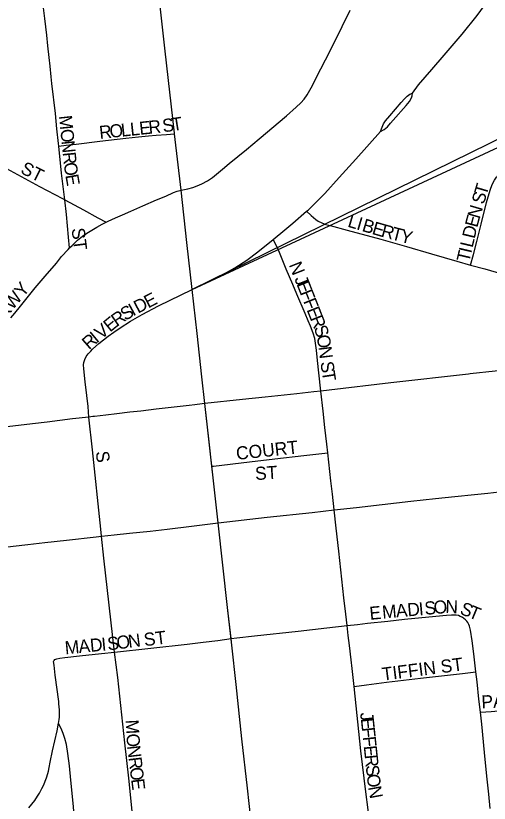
# Model space of a CAD drawing. Extents: x 1772825 to 1773716, y 1138558 to 1139032.
# Drawn here: x 1773349.44 to 1773356.3, y 1138869.86 to 1138881.27 of the extents above; entities that cross this region are included whole.
import ezdxf

# ---------------------------------------------------------------- set-up
doc = ezdxf.new("R2010")
doc.units = 0
for name, color, linetype in [('Default', 7, 'Continuous'), ('GM_X_City_Street', 7, 'Continuous'), ('GM_X_City_Street_Text', 7, 'Continuous'), ('GM_X_State_Route', 7, 'Continuous'), ('SH_Text', 7, 'Continuous')]:
    doc.layers.add(name, color=color, linetype=linetype)

msp = doc.modelspace()

# ---------------------------------------------------------------- linework, layer by layer
at = {"layer": 'Default'}
msp.add_lwpolyline([(1773353.166, 1138866.864), (1773353.051, 1138867.771), (1773352.988, 1138868.345), (1773352.939, 1138868.791), (1773352.873, 1138869.411), (1773352.801, 1138870.079), (1773352.718, 1138870.795), (1773352.633, 1138871.579), (1773352.571, 1138872.151), (1773352.507, 1138872.699), (1773352.374, 1138873.925), (1773352.299, 1138874.578), (1773352.18, 1138875.654), (1773352.138, 1138876.039), (1773352.067, 1138876.669), (1773351.996, 1138877.306)], dxfattribs=at)
at = {"layer": 'GM_X_City_Street'}
for points in [[(1773355.189, 1138880.149), (1773355.278, 1138880.269), (1773355.47, 1138880.493), (1773355.648, 1138880.701), (1773355.912, 1138881.003), (1773356.126, 1138881.277), (1773356.326, 1138881.548), (1773356.534, 1138881.839), (1773356.632, 1138881.983), (1773356.777, 1138882.213), (1773356.866, 1138882.373), (1773356.933, 1138882.503)], [(1773350.064, 1138879.383), (1773350.06, 1138879.422), (1773350.036, 1138879.631), (1773350.015, 1138879.853), (1773349.964, 1138880.291), (1773349.954, 1138880.386), (1773349.937, 1138880.543), (1773349.922, 1138880.665), (1773349.907, 1138880.837), (1773349.891, 1138880.99), (1773349.863, 1138881.232), (1773349.836, 1138881.423), (1773349.823, 1138881.513)], [(1773351.835, 1138878.745), (1773351.932, 1138878.765), (1773352.004, 1138878.784), (1773352.069, 1138878.806), (1773352.137, 1138878.835), (1773352.217, 1138878.878), (1773352.25, 1138878.9), (1773352.289, 1138878.929), (1773352.436, 1138879.048), (1773352.533, 1138879.129), (1773352.782, 1138879.332), (1773352.97, 1138879.487), (1773353.364, 1138879.823), (1773353.503, 1138879.947), (1773353.573, 1138880.009), (1773353.619, 1138880.064), (1773353.663, 1138880.126), (1773353.72, 1138880.229), (1773353.862, 1138880.503), (1773353.996, 1138880.761), (1773354.172, 1138881.116), (1773354.289, 1138881.35)], [(1773354.728, 1138879.594), (1773354.78, 1138879.624), (1773354.827, 1138879.661), (1773354.872, 1138879.713), (1773354.912, 1138879.76), (1773355.098, 1138879.972), (1773355.145, 1138880.031), (1773355.177, 1138880.08), (1773355.184, 1138880.11), (1773355.189, 1138880.149)], [(1773354.728, 1138879.594), (1773354.75, 1138879.658), (1773354.772, 1138879.707), (1773354.797, 1138879.747), (1773354.863, 1138879.82), (1773355.026, 1138880.016), (1773355.073, 1138880.068), (1773355.113, 1138880.105), (1773355.152, 1138880.134), (1773355.189, 1138880.149)], [(1773350.064, 1138879.383), (1773350.17, 1138879.395), (1773350.313, 1138879.412), (1773350.656, 1138879.452), (1773351.033, 1138879.498), (1773351.221, 1138879.519), (1773351.366, 1138879.532), (1773351.477, 1138879.541), (1773351.626, 1138879.551), (1773351.743, 1138879.558)], [(1773353.656, 1138878.438), (1773353.677, 1138878.456), (1773353.918, 1138878.698), (1773354.126, 1138878.929), (1773354.368, 1138879.193), (1773354.728, 1138879.594)], [(1773348.497, 1138879.489), (1773348.622, 1138879.421), (1773348.846, 1138879.306), (1773349.307, 1138879.058), (1773349.786, 1138878.799), (1773350.116, 1138878.624), (1773350.15, 1138878.606)], [(1773350.15, 1138878.606), (1773350.105, 1138878.991), (1773350.064, 1138879.383)], [(1773356.033, 1138877.659), (1773356.074, 1138877.812), (1773356.123, 1138877.999), (1773356.186, 1138878.252), (1773356.264, 1138878.564), (1773356.316, 1138878.742), (1773356.346, 1138878.824), (1773356.379, 1138878.89), (1773356.407, 1138878.931), (1773356.421, 1138878.949), (1773356.442, 1138878.97)], [(1773350.749, 1138878.278), (1773350.781, 1138878.294), (1773350.883, 1138878.341), (1773350.989, 1138878.389), (1773351.107, 1138878.441), (1773351.28, 1138878.517), (1773351.482, 1138878.605), (1773351.613, 1138878.659), (1773351.727, 1138878.71), (1773351.779, 1138878.73), (1773351.835, 1138878.745)], [(1773350.15, 1138878.606), (1773350.422, 1138878.459), (1773350.628, 1138878.345), (1773350.749, 1138878.278)], [(1773350.221, 1138877.907), (1773350.206, 1138878.061), (1773350.174, 1138878.392), (1773350.15, 1138878.606)], [(1773353.173, 1138878.03), (1773353.342, 1138878.17), (1773353.457, 1138878.267), (1773353.656, 1138878.438)], [(1773353.656, 1138878.438), (1773353.723, 1138878.378), (1773353.754, 1138878.35), (1773353.787, 1138878.321), (1773353.822, 1138878.297), (1773353.878, 1138878.269), (1773353.936, 1138878.248), (1773353.996, 1138878.231), (1773354.244, 1138878.166), (1773354.732, 1138878.035), (1773355.101, 1138877.928), (1773355.468, 1138877.823), (1773355.835, 1138877.717), (1773356.033, 1138877.659)], [(1773350.221, 1138877.907), (1773350.256, 1138877.941), (1773350.333, 1138878.018), (1773350.408, 1138878.079), (1773350.468, 1138878.121), (1773350.616, 1138878.21), (1773350.693, 1138878.25), (1773350.749, 1138878.278)], [(1773351.996, 1138877.306), (1773352.09, 1138877.35), (1773352.281, 1138877.44), (1773352.459, 1138877.533), (1773352.617, 1138877.617), (1773352.788, 1138877.73), (1773352.95, 1138877.849), (1773353.173, 1138878.03)], [(1773353.864, 1138875.831), (1773353.833, 1138876.098), (1773353.814, 1138876.276), (1773353.798, 1138876.427), (1773353.786, 1138876.525), (1773353.773, 1138876.595), (1773353.749, 1138876.674), (1773353.71, 1138876.775), (1773353.677, 1138876.853), (1773353.635, 1138876.955), (1773353.515, 1138877.239), (1773353.456, 1138877.375), (1773353.36, 1138877.601), (1773353.264, 1138877.84), (1773353.235, 1138877.907), (1773353.173, 1138878.03)], [(1773349.366, 1138876.894), (1773349.425, 1138876.963), (1773349.508, 1138877.064), (1773349.723, 1138877.327), (1773349.868, 1138877.496), (1773350.03, 1138877.688), (1773350.105, 1138877.781), (1773350.199, 1138877.885), (1773350.221, 1138877.907)], [(1773356.033, 1138877.659), (1773356.238, 1138877.602), (1773356.565, 1138877.509), (1773356.837, 1138877.435), (1773357.283, 1138877.314), (1773357.656, 1138877.205), (1773357.936, 1138877.121), (1773358.119, 1138877.064), (1773358.274, 1138877.016)], [(1773350.49, 1138876.371), (1773350.528, 1138876.413), (1773350.554, 1138876.439), (1773350.645, 1138876.521), (1773350.781, 1138876.629), (1773350.863, 1138876.688), (1773350.952, 1138876.751), (1773351.103, 1138876.844), (1773351.271, 1138876.942), (1773351.51, 1138877.069), (1773351.996, 1138877.306)], [(1773350.501, 1138875.456), (1773350.487, 1138875.609), (1773350.472, 1138875.77), (1773350.447, 1138875.969), (1773350.425, 1138876.153), (1773350.423, 1138876.213), (1773350.428, 1138876.247), (1773350.442, 1138876.291), (1773350.462, 1138876.333), (1773350.49, 1138876.371)], [(1773353.962, 1138874.939), (1773353.949, 1138875.065), (1773353.922, 1138875.307), (1773353.897, 1138875.541), (1773353.864, 1138875.831)], [(1773350.683, 1138873.731), (1773350.673, 1138873.831), (1773350.553, 1138874.98), (1773350.501, 1138875.456)], [(1773352.281, 1138874.744), (1773352.305, 1138874.747), (1773352.827, 1138874.81), (1773353.197, 1138874.851), (1773353.614, 1138874.898), (1773353.962, 1138874.939)], [(1773354.054, 1138874.11), (1773354.03, 1138874.337), (1773354.005, 1138874.532), (1773353.962, 1138874.939)], [(1773354.243, 1138872.434), (1773354.224, 1138872.6), (1773354.196, 1138872.838), (1773354.167, 1138873.107), (1773354.121, 1138873.513), (1773354.083, 1138873.847), (1773354.054, 1138874.11)], [(1773350.873, 1138872.052), (1773350.716, 1138873.411), (1773350.683, 1138873.731)], [(1773354.243, 1138872.434), (1773354.392, 1138872.452), (1773354.536, 1138872.469), (1773354.832, 1138872.501), (1773355.073, 1138872.529), (1773355.427, 1138872.564), (1773355.681, 1138872.587), (1773355.755, 1138872.592), (1773355.785, 1138872.592), (1773355.823, 1138872.59), (1773355.857, 1138872.584), (1773355.883, 1138872.573), (1773355.909, 1138872.558)], [(1773356.109, 1138871.766), (1773356.105, 1138871.807), (1773356.08, 1138872.028), (1773356.056, 1138872.212), (1773356.03, 1138872.371), (1773356.017, 1138872.426), (1773356.007, 1138872.453), (1773355.993, 1138872.478), (1773355.979, 1138872.497), (1773355.958, 1138872.52), (1773355.936, 1138872.539), (1773355.909, 1138872.558)], [(1773352.56, 1138872.249), (1773352.644, 1138872.258), (1773352.899, 1138872.286), (1773353.532, 1138872.356), (1773353.951, 1138872.402), (1773354.243, 1138872.434)], [(1773354.343, 1138871.551), (1773354.315, 1138871.811), (1773354.301, 1138871.939), (1773354.276, 1138872.145), (1773354.26, 1138872.29), (1773354.243, 1138872.434)], [(1773350.873, 1138872.052), (1773351.924, 1138872.168), (1773352.155, 1138872.193), (1773352.369, 1138872.22), (1773352.56, 1138872.249)], [(1773350.005, 1138871.945), (1773350.037, 1138871.954), (1773350.08, 1138871.965), (1773350.153, 1138871.973), (1773350.363, 1138871.996), (1773350.683, 1138872.031), (1773350.873, 1138872.052)], [(1773351.305, 1138868.153), (1773351.299, 1138868.204), (1773351.244, 1138868.698), (1773351.188, 1138869.19), (1773351.167, 1138869.362), (1773351.077, 1138870.226), (1773351.02, 1138870.738), (1773350.917, 1138871.684), (1773350.873, 1138872.052)], [(1773350.06, 1138871.021), (1773350.064, 1138871.039), (1773350.069, 1138871.077), (1773350.072, 1138871.101), (1773350.074, 1138871.143), (1773350.074, 1138871.179), (1773350.073, 1138871.215), (1773350.066, 1138871.299), (1773350.062, 1138871.336), (1773350.012, 1138871.717), (1773349.995, 1138871.86), (1773349.989, 1138871.913), (1773349.991, 1138871.922), (1773349.994, 1138871.93), (1773350.005, 1138871.945)], [(1773354.343, 1138871.551), (1773354.524, 1138871.575), (1773354.815, 1138871.613), (1773355.304, 1138871.671), (1773355.697, 1138871.717), (1773355.913, 1138871.742), (1773356.109, 1138871.766)], [(1773356.175, 1138871.181), (1773356.154, 1138871.37), (1773356.126, 1138871.62), (1773356.109, 1138871.766)], [(1773354.565, 1138869.601), (1773354.546, 1138869.763), (1773354.516, 1138870.026), (1773354.442, 1138870.621), (1773354.343, 1138871.551)], [(1773356.175, 1138871.181), (1773356.332, 1138871.192), (1773356.8, 1138871.236), (1773357.19, 1138871.276), (1773357.566, 1138871.316), (1773357.78, 1138871.339)], [(1773356.318, 1138869.787), (1773356.297, 1138869.993), (1773356.27, 1138870.255), (1773356.235, 1138870.597), (1773356.193, 1138871.007), (1773356.175, 1138871.181)], [(1773349.629, 1138869.796), (1773349.716, 1138869.9), (1773349.757, 1138869.961), (1773349.783, 1138870.005), (1773349.82, 1138870.076), (1773349.847, 1138870.128), (1773349.868, 1138870.181), (1773349.885, 1138870.23), (1773349.903, 1138870.29), (1773349.913, 1138870.327), (1773349.925, 1138870.38), (1773349.94, 1138870.454), (1773349.972, 1138870.618), (1773350.038, 1138870.909), (1773350.06, 1138871.021)], [(1773350.466, 1138868.065), (1773350.456, 1138868.17), (1773350.428, 1138868.453), (1773350.391, 1138868.786), (1773350.348, 1138869.157), (1773350.293, 1138869.639), (1773350.272, 1138869.862), (1773350.237, 1138870.195), (1773350.218, 1138870.405), (1773350.194, 1138870.581), (1773350.173, 1138870.711), (1773350.153, 1138870.801), (1773350.128, 1138870.873), (1773350.108, 1138870.918), (1773350.06, 1138871.021)]]:
    msp.add_lwpolyline(points, dxfattribs=at)
at = {"layer": 'GM_X_State_Route'}
for points in [[(1773352.374, 1138873.925), (1773352.299, 1138874.578), (1773352.281, 1138874.744), (1773352.241, 1138875.098), (1773352.18, 1138875.654), (1773352.138, 1138876.039), (1773352.067, 1138876.669), (1773351.996, 1138877.306), (1773351.919, 1138877.988), (1773351.835, 1138878.745), (1773351.743, 1138879.558), (1773351.742, 1138879.571), (1773351.603, 1138880.757), (1773351.523, 1138881.499)], [(1773360.609, 1138876.652), (1773359.957, 1138876.572), (1773359.408, 1138876.505), (1773358.443, 1138876.362), (1773358.286, 1138876.343), (1773357.766, 1138876.278), (1773357.182, 1138876.206), (1773356.908, 1138876.173), (1773356.388, 1138876.119), (1773356.026, 1138876.082)], [(1773356.026, 1138876.082), (1773356, 1138876.079), (1773354.876, 1138875.951), (1773353.983, 1138875.845)], [(1773353.983, 1138875.845), (1773353.864, 1138875.831), (1773353.76, 1138875.82), (1773353.516, 1138875.793), (1773353.055, 1138875.745), (1773352.728, 1138875.711), (1773352.18, 1138875.654), (1773352.142, 1138875.648), (1773352.036, 1138875.633), (1773351.951, 1138875.623), (1773351.865, 1138875.613), (1773351.737, 1138875.599), (1773351.476, 1138875.569), (1773351.253, 1138875.544), (1773351.094, 1138875.526), (1773350.907, 1138875.503), (1773350.747, 1138875.485), (1773350.58, 1138875.466)], [(1773350.58, 1138875.466), (1773350.557, 1138875.463), (1773350.501, 1138875.456), (1773350.263, 1138875.429), (1773349.896, 1138875.384), (1773349.683, 1138875.359), (1773349.313, 1138875.315)], [(1773354.054, 1138874.11), (1773354.38, 1138874.147), (1773354.751, 1138874.189), (1773355.168, 1138874.236), (1773355.523, 1138874.275), (1773355.804, 1138874.304), (1773356.09, 1138874.334), (1773356.282, 1138874.355), (1773356.61, 1138874.392)], [(1773352.374, 1138873.925), (1773353.083, 1138874.004), (1773353.737, 1138874.075), (1773354.054, 1138874.11)], [(1773348.05, 1138873.416), (1773348.366, 1138873.456), (1773348.638, 1138873.489), (1773349.083, 1138873.545), (1773349.401, 1138873.584), (1773349.613, 1138873.61), (1773349.861, 1138873.638), (1773350.177, 1138873.674), (1773350.605, 1138873.723), (1773350.683, 1138873.731), (1773350.866, 1138873.751), (1773351.09, 1138873.774), (1773351.388, 1138873.804), (1773351.636, 1138873.832), (1773351.986, 1138873.875), (1773352.374, 1138873.925)], [(1773353.166, 1138866.864), (1773353.051, 1138867.771), (1773352.988, 1138868.345), (1773352.939, 1138868.791), (1773352.873, 1138869.411), (1773352.801, 1138870.079), (1773352.718, 1138870.795), (1773352.633, 1138871.579), (1773352.571, 1138872.151), (1773352.56, 1138872.249), (1773352.507, 1138872.699), (1773352.374, 1138873.925)]]:
    msp.add_lwpolyline(points, dxfattribs=at)
at = {"layer": 'SH_Text'}
msp.add_lwpolyline([(1773543.413, 1138971.185), (1773351.996, 1138877.306), (1773543.413, 1138966.239)], close=True, dxfattribs=at)

# ---------------------------------------------------------------- texts
at = {"layer": 'GM_X_City_Street_Text'}
for s, height, rotation, p in [('M', 0.189, 275.8574, (1773350.065, 1138879.82)), ('S', 0.189, 7.712, (1773351.577, 1138879.581)), ('T', 0.189, 8.9159, (1773351.714, 1138879.599)), ('R', 0.189, 5.9111, (1773350.659, 1138879.485)), ('O', 0.189, 5.9256, (1773350.808, 1138879.501)), ('L', 0.189, 5.9118, (1773350.974, 1138879.518)), ('L', 0.189, 5.9209, (1773351.107, 1138879.531)), ('E', 0.189, 5.9118, (1773351.239, 1138879.545)), ('R', 0.189, 5.9236, (1773351.372, 1138879.559)), ('O', 0.189, 275.8454, (1773350.085, 1138879.621)), ('N', 0.189, 275.8586, (1773350.102, 1138879.455)), ('R', 0.189, 275.8387, (1773350.119, 1138879.289)), ('ST', 0.1894, 333.435, (1773349.495, 1138878.998)), ('O', 0.189, 277.0973, (1773350.135, 1138879.136)), ('E', 0.189, 279.8587, (1773350.157, 1138878.96)), ('T', 0.189, 73.6043, (1773356.262, 1138878.656)), ('S', 0.189, 73.6264, (1773356.224, 1138878.528)), ('N', 0.189, 73.7153, (1773356.163, 1138878.32)), ('L', 0.189, 343.3191, (1773354.239, 1138878.217)), ('I', 0.189, 343.3498, (1773354.367, 1138878.179)), ('B', 0.189, 343.324, (1773354.447, 1138878.155)), ('E', 0.189, 343.5948, (1773354.592, 1138878.112)), ('E', 0.189, 75.1953, (1773356.129, 1138878.193)), ('ST', 0.1894, 277.12, (1773350.248, 1138878.187)), ('R', 0.189, 344.926, (1773354.724, 1138878.073)), ('T', 0.189, 345.4074, (1773354.871, 1138878.033)), ('Y', 0.189, 345.453, (1773355, 1138878)), ('D', 0.189, 76.7213, (1773356.091, 1138878.032)), ('L', 0.189, 76.7125, (1773356.061, 1138877.902)), ('T', 0.189, 76.7391, (1773356.011, 1138877.691)), ('I', 0.189, 76.7269, (1773356.042, 1138877.821)), ('N', 0.189, 291.5538, (1773353.395, 1138877.663)), ('J', 0.189, 291.5741, (1773353.475, 1138877.462)), ('FROST PKWY', 0.1894, 50.3565, (1773348.585, 1138876.023)), ('E', 0.189, 291.5496, (1773353.506, 1138877.384)), ('E', 0.189, 27.0905, (1773351.359, 1138877.029)), ('F', 0.189, 291.5735, (1773353.555, 1138877.26)), ('D', 0.189, 27.3666, (1773351.211, 1138876.953)), ('F', 0.189, 291.5731, (1773353.604, 1138877.136)), ('S', 0.189, 30.9684, (1773351.026, 1138876.846)), ('I', 0.189, 28.7361, (1773351.139, 1138876.913)), ('E', 0.189, 291.5376, (1773353.653, 1138877.012)), ('E', 0.189, 39.2777, (1773350.806, 1138876.679)), ('R', 0.189, 34.99, (1773350.906, 1138876.761)), ('R', 0.189, 291.562, (1773353.702, 1138876.888)), ('V', 0.189, 39.2709, (1773350.677, 1138876.574)), ('I', 0.189, 39.8, (1773350.613, 1138876.521)), ('S', 0.189, 289.9294, (1773353.756, 1138876.75)), ('R', 0.189, 41.2544, (1773350.502, 1138876.423)), ('O', 0.189, 279.775, (1773353.799, 1138876.633)), ('N', 0.189, 276.7916, (1773353.827, 1138876.472)), ('S', 0.189, 278.4014, (1773353.854, 1138876.251)), ('T', 0.189, 278.7527, (1773353.874, 1138876.118)), ('COURT', 0.1894, 6.073, (1773352.643, 1138874.835)), ('S', 0.189, 277.1183, (1773350.598, 1138874.954)), ('ST', 0.1894, 3.5746, (1773352.914, 1138874.543)), ('O', 0.189, 5.0123, (1773355.505, 1138872.602)), ('N', 0.189, 358.4477, (1773355.665, 1138872.616)), ('E', 0.189, 5.1425, (1773354.575, 1138872.518)), ('M', 0.189, 5.121, (1773354.758, 1138872.535)), ('A', 0.189, 5.1324, (1773354.957, 1138872.553)), ('D', 0.189, 5.1212, (1773355.123, 1138872.568)), ('I', 0.189, 5.1232, (1773355.289, 1138872.582)), ('S', 0.189, 5.1322, (1773355.372, 1138872.59)), ('S', 0.189, 338.4624, (1773355.864, 1138872.609)), ('T', 0.189, 337.7165, (1773355.987, 1138872.56)), ('ST', 0.1894, 7.12, (1773351.308, 1138872.135)), ('A', 0.189, 5.3461, (1773350.358, 1138872.037)), ('D', 0.189, 5.3191, (1773350.524, 1138872.053)), ('I', 0.189, 5.3496, (1773350.69, 1138872.068)), ('S', 0.189, 6.0711, (1773350.776, 1138872.076)), ('O', 0.189, 7.2214, (1773350.912, 1138872.091)), ('N', 0.189, 7.4379, (1773351.079, 1138872.112)), ('M', 0.189, 5.3264, (1773350.159, 1138872.018)), ('TIFFIN ST', 0.1894, 7.3513, (1773354.759, 1138871.635)), ('PARK', 0.1894, 3.1778, (1773356.194, 1138871.233)), ('J', 0.189, 276.0456, (1773354.431, 1138871.17)), ('M', 0.189, 272.9333, (1773351.031, 1138871.068)), ('E', 0.189, 276.0205, (1773354.44, 1138871.087)), ('F', 0.189, 276.0461, (1773354.454, 1138870.954)), ('O', 0.189, 274.0433, (1773351.042, 1138870.864)), ('F', 0.189, 276.0461, (1773354.468, 1138870.822)), ('N', 0.189, 276.5496, (1773351.054, 1138870.689)), ('E', 0.189, 276.0205, (1773354.482, 1138870.689)), ('R', 0.189, 276.8416, (1773351.074, 1138870.522)), ('R', 0.189, 276.0419, (1773354.496, 1138870.556)), ('O', 0.189, 276.8457, (1773351.091, 1138870.373)), ('S', 0.189, 276.0461, (1773354.512, 1138870.407)), ('E', 0.189, 276.8475, (1773351.111, 1138870.208)), ('O', 0.189, 276.0433, (1773354.526, 1138870.275)), ('N', 0.189, 280.3612, (1773354.546, 1138870.094))]:
    msp.add_text(s, height=height, rotation=rotation, dxfattribs=at).set_placement(p)

doc.saveas('drawing.dxf')
